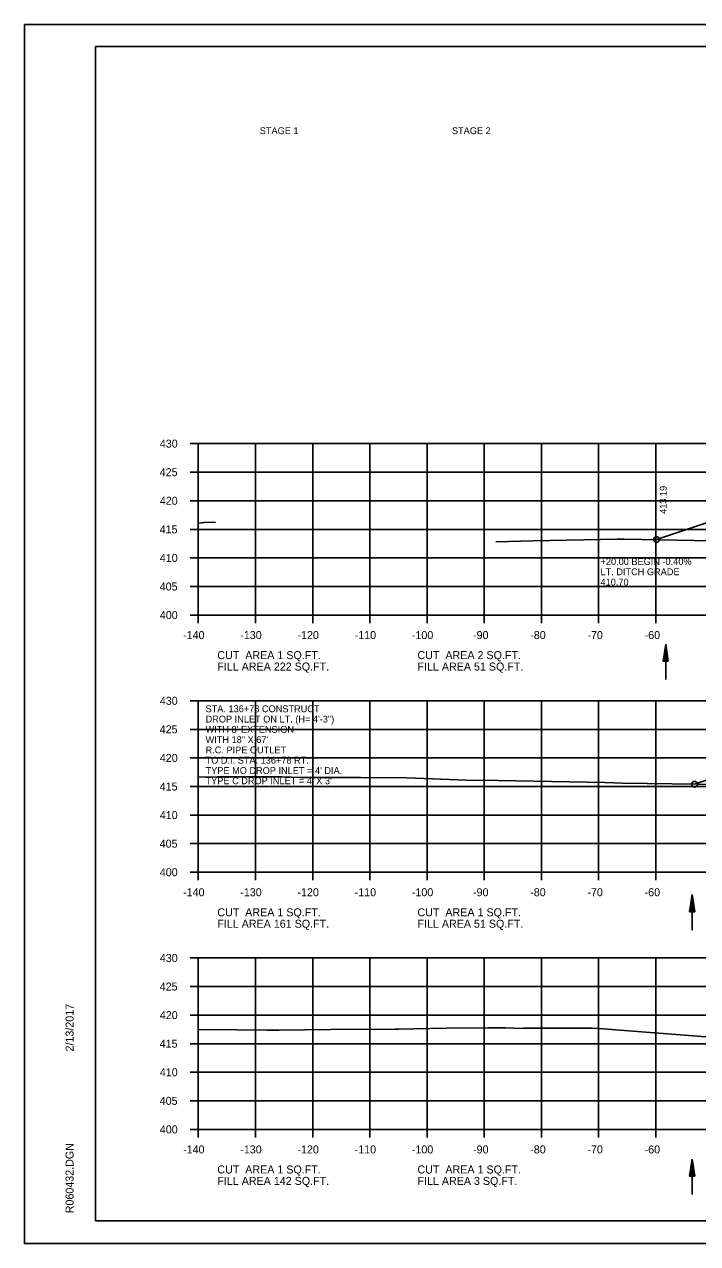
# Model space of a CAD drawing. Extents: x 1538688 to 1540766, y 656250 to 671912.
# Drawn here: x 1538687.8 to 1538805.5, y 661671.3 to 661884.7 of the extents above; entities that cross this region are included whole.
import ezdxf

# ---------------------------------------------------------------- set-up
doc = ezdxf.new("R2010")
doc.units = 0
for name, color, linetype in [('15', 7, 'Continuous'), ('18', 7, 'Continuous'), ('20', 7, 'Continuous'), ('22', 7, 'Continuous'), ('26', 7, 'Continuous'), ('39', 7, 'Continuous'), ('40', 7, 'Continuous'), ('41', 7, 'Continuous'), ('Borings', 7, 'Continuous'), ('Default', 7, 'Continuous'), ('Horizontal Alignment', 7, 'Continuous'), ('RipRap', 7, 'Continuous')]:
    doc.layers.add(name, color=color, linetype=linetype)

msp = doc.modelspace()

# ---------------------------------------------------------------- linework, layer by layer
at = {"layer": '15'}
for p, q in [((1538799.46, 661773.26), (1538799.91, 661776.26)), ((1538799.54, 661773.26), (1538799.91, 661775.76)), ((1538800.36, 661773.26), (1538799.91, 661776.26)), ((1538800.29, 661773.26), (1538799.91, 661775.76)), ((1538799.46, 661773.26), (1538800.36, 661773.26)), ((1538799.61, 661773.26), (1538799.91, 661775.24)), ((1538799.69, 661773.26), (1538799.91, 661774.74)), ((1538799.77, 661773.26), (1538799.91, 661774.24)), ((1538799.84, 661773.26), (1538799.91, 661773.73)), ((1538800.21, 661773.26), (1538799.91, 661775.24)), ((1538800.14, 661773.26), (1538799.91, 661774.74)), ((1538800.06, 661773.26), (1538799.91, 661774.24)), ((1538799.98, 661773.26), (1538799.91, 661773.73)), ((1538804.09, 661729.41), (1538804.54, 661732.41)), ((1538804.17, 661729.41), (1538804.54, 661731.91)), ((1538804.24, 661729.41), (1538804.54, 661731.39)), ((1538804.32, 661729.41), (1538804.54, 661730.89)), ((1538804.99, 661729.41), (1538804.54, 661732.41)), ((1538804.92, 661729.41), (1538804.54, 661731.91)), ((1538804.84, 661729.41), (1538804.54, 661731.39)), ((1538804.77, 661729.41), (1538804.54, 661730.89)), ((1538804.09, 661729.41), (1538804.99, 661729.41)), ((1538804.4, 661729.41), (1538804.54, 661730.38)), ((1538804.47, 661729.41), (1538804.54, 661729.88)), ((1538804.69, 661729.41), (1538804.54, 661730.38)), ((1538804.61, 661729.41), (1538804.54, 661729.88)), ((1538804.09, 661683.15), (1538804.54, 661686.15)), ((1538804.99, 661683.15), (1538804.54, 661686.15)), ((1538804.17, 661683.15), (1538804.54, 661685.65)), ((1538804.24, 661683.15), (1538804.54, 661685.14)), ((1538804.32, 661683.15), (1538804.54, 661684.64)), ((1538804.4, 661683.15), (1538804.54, 661684.13)), ((1538804.92, 661683.15), (1538804.54, 661685.65)), ((1538804.84, 661683.15), (1538804.54, 661685.14)), ((1538804.77, 661683.15), (1538804.54, 661684.64)), ((1538804.69, 661683.15), (1538804.54, 661684.13)), ((1538804.09, 661683.15), (1538804.99, 661683.15)), ((1538804.47, 661683.15), (1538804.54, 661683.63)), ((1538804.61, 661683.15), (1538804.54, 661683.63))]:
    msp.add_line(p, q, dxfattribs=at)
at = {"layer": '18'}
for points in [[(1538718.18, 661797.42), (1538719.22, 661797.53), (1538721.2, 661797.58)], [(1538770.19, 661794.16), (1538776.77, 661794.33), (1538791.41, 661794.6), (1538792.64, 661794.63), (1538807.97, 661794.34)], [(1538718.18, 661753.03), (1538718.2, 661753.03), (1538721.42, 661752.99), (1538721.56, 661753.01), (1538732.85, 661753.02), (1538736.02, 661752.93), (1538746.52, 661752.88), (1538754.65, 661752.85), (1538765.08, 661752.43), (1538770.59, 661752.36), (1538789.25, 661752.02), (1538792.37, 661751.89), (1538809.68, 661751.66)], [(1538718.18, 661708.83), (1538724.92, 661708.73), (1538730.21, 661708.69), (1538731.39, 661708.7), (1538732.31, 661708.68), (1538741.29, 661708.79), (1538752.54, 661708.88), (1538753.27, 661708.85), (1538755.88, 661708.94), (1538761.65, 661709.02), (1538768.86, 661709.1), (1538771.88, 661709.11), (1538774.68, 661709), (1538775.07, 661709.03), (1538786.4, 661709.06), (1538787.13, 661709.06), (1538788.24, 661708.98), (1538830.89, 661705.68)]]:
    msp.add_lwpolyline(points, dxfattribs=at)
at = {"layer": '20'}
for points in [[(1538798.28, 661794.53), (1538816.67, 661800.65), (1538821.67, 661800.55), (1538824.67, 661800.49), (1538825.17, 661800.49), (1538825.18, 661799.99), (1538826.18, 661800.01), (1538858.18, 661800.65), (1538890.18, 661800.01), (1538891.18, 661799.99), (1538891.19, 661800.49), (1538891.69, 661800.49), (1538894.69, 661800.55), (1538899.69, 661800.65), (1538914.02, 661795.88)], [(1538804.95, 661751.72), (1538816.67, 661755.63), (1538821.67, 661755.53), (1538824.67, 661755.47), (1538825.17, 661755.47), (1538825.18, 661754.97), (1538826.18, 661754.99), (1538858.18, 661755.63), (1538890.18, 661754.99), (1538891.18, 661754.97), (1538891.19, 661755.47), (1538891.69, 661755.47), (1538894.69, 661755.53), (1538899.69, 661755.63), (1538911.37, 661751.74)]]:
    msp.add_lwpolyline(points, dxfattribs=at)
at = {"layer": '22'}
for p, q in [((1538718.18, 661811.33), (1538998.18, 661811.33)), ((1538718.18, 661781.33), (1538718.18, 661811.33)), ((1538728.18, 661781.33), (1538728.18, 661811.33)), ((1538738.18, 661781.33), (1538738.18, 661811.33)), ((1538748.18, 661781.33), (1538748.18, 661811.33)), ((1538758.18, 661781.33), (1538758.18, 661811.33)), ((1538768.18, 661781.33), (1538768.18, 661811.33)), ((1538778.18, 661781.33), (1538778.18, 661811.33)), ((1538788.18, 661781.33), (1538788.18, 661811.33)), ((1538798.18, 661781.33), (1538798.18, 661811.33)), ((1538718.18, 661806.33), (1538998.18, 661806.33)), ((1538718.18, 661801.33), (1538998.18, 661801.33)), ((1538718.18, 661796.33), (1538998.18, 661796.33)), ((1538718.18, 661791.33), (1538998.18, 661791.33)), ((1538718.18, 661786.33), (1538998.18, 661786.33)), ((1538718.18, 661781.33), (1538998.18, 661781.33)), ((1538718.18, 661766.33), (1538998.18, 661766.33)), ((1538718.18, 661736.33), (1538718.18, 661766.33)), ((1538728.18, 661736.33), (1538728.18, 661766.33)), ((1538738.18, 661736.33), (1538738.18, 661766.33)), ((1538748.18, 661736.33), (1538748.18, 661766.33)), ((1538758.18, 661736.33), (1538758.18, 661766.33)), ((1538768.18, 661736.33), (1538768.18, 661766.33)), ((1538778.18, 661736.33), (1538778.18, 661766.33)), ((1538788.18, 661736.33), (1538788.18, 661766.33)), ((1538798.18, 661736.33), (1538798.18, 661766.33)), ((1538718.18, 661761.33), (1538998.18, 661761.33)), ((1538718.18, 661756.33), (1538998.18, 661756.33)), ((1538718.18, 661751.33), (1538998.18, 661751.33)), ((1538718.18, 661746.33), (1538998.18, 661746.33)), ((1538718.18, 661741.33), (1538998.18, 661741.33)), ((1538718.18, 661736.33), (1538998.18, 661736.33)), ((1538718.18, 661721.33), (1538998.18, 661721.33)), ((1538718.18, 661691.33), (1538718.18, 661721.33)), ((1538728.18, 661691.33), (1538728.18, 661721.33)), ((1538738.18, 661691.33), (1538738.18, 661721.33)), ((1538748.18, 661691.33), (1538748.18, 661721.33)), ((1538758.18, 661691.33), (1538758.18, 661721.33)), ((1538768.18, 661691.33), (1538768.18, 661721.33)), ((1538778.18, 661691.33), (1538778.18, 661721.33)), ((1538788.18, 661691.33), (1538788.18, 661721.33)), ((1538798.18, 661691.33), (1538798.18, 661721.33)), ((1538718.18, 661716.33), (1538998.18, 661716.33)), ((1538718.18, 661711.33), (1538998.18, 661711.33)), ((1538718.18, 661706.33), (1538998.18, 661706.33)), ((1538718.18, 661701.33), (1538998.18, 661701.33)), ((1538718.18, 661696.33), (1538998.18, 661696.33)), ((1538718.18, 661691.33), (1538998.18, 661691.33))]:
    msp.add_line(p, q, dxfattribs=at)
at = {"layer": '26'}
for p, q in [((1538687.78, 661884.68), (1539021.11, 661884.68)), ((1538687.78, 661671.35), (1539021.11, 661671.35))]:
    msp.add_line(p, q, dxfattribs=at)
msp.add_lwpolyline([(1538687.77, 661884.68), (1539021.11, 661884.68), (1539021.11, 661671.35), (1538687.77, 661671.35)], close=True, dxfattribs=at)
for centre in [(1538798.28, 661794.53), (1538804.95, 661751.72)]:
    msp.add_circle(centre, 0.5, dxfattribs=at)
at = {"layer": '39'}
for p, q in [((1538799.91, 661770.07), (1538799.91, 661776.26)), ((1538804.54, 661726.22), (1538804.54, 661732.41)), ((1538804.54, 661679.97), (1538804.54, 661686.15))]:
    msp.add_line(p, q, dxfattribs=at)
at = {"layer": 'Borings'}
for p, q in [((1538716.78, 661811.33), (1538718.18, 661811.33)), ((1538718.18, 661781.33), (1538718.18, 661811.33)), ((1538716.78, 661806.33), (1538718.18, 661806.33)), ((1538716.78, 661801.33), (1538718.18, 661801.33)), ((1538716.78, 661796.33), (1538718.18, 661796.33)), ((1538716.78, 661791.33), (1538718.18, 661791.33)), ((1538716.78, 661786.33), (1538718.18, 661786.33)), ((1538716.78, 661781.33), (1538718.18, 661781.33)), ((1538718.18, 661781.33), (1538998.18, 661781.33)), ((1538718.18, 661779.93), (1538718.18, 661781.33)), ((1538728.18, 661779.93), (1538728.18, 661781.33)), ((1538738.18, 661779.93), (1538738.18, 661781.33)), ((1538748.18, 661779.93), (1538748.18, 661781.33)), ((1538758.18, 661779.93), (1538758.18, 661781.33)), ((1538768.18, 661779.93), (1538768.18, 661781.33)), ((1538778.18, 661779.93), (1538778.18, 661781.33)), ((1538788.18, 661779.93), (1538788.18, 661781.33)), ((1538798.18, 661779.93), (1538798.18, 661781.33)), ((1538716.78, 661766.33), (1538718.18, 661766.33)), ((1538718.18, 661736.33), (1538718.18, 661766.33)), ((1538716.78, 661761.33), (1538718.18, 661761.33)), ((1538716.78, 661756.33), (1538718.18, 661756.33)), ((1538716.78, 661751.33), (1538718.18, 661751.33)), ((1538716.78, 661746.33), (1538718.18, 661746.33)), ((1538716.78, 661741.33), (1538718.18, 661741.33)), ((1538716.78, 661736.33), (1538718.18, 661736.33)), ((1538718.18, 661736.33), (1538998.18, 661736.33)), ((1538718.18, 661734.93), (1538718.18, 661736.33)), ((1538728.18, 661734.93), (1538728.18, 661736.33)), ((1538738.18, 661734.93), (1538738.18, 661736.33)), ((1538748.18, 661734.93), (1538748.18, 661736.33)), ((1538758.18, 661734.93), (1538758.18, 661736.33)), ((1538768.18, 661734.93), (1538768.18, 661736.33)), ((1538778.18, 661734.93), (1538778.18, 661736.33)), ((1538788.18, 661734.93), (1538788.18, 661736.33)), ((1538798.18, 661734.93), (1538798.18, 661736.33)), ((1538716.78, 661721.33), (1538718.18, 661721.33)), ((1538718.18, 661691.33), (1538718.18, 661721.33)), ((1538716.78, 661716.33), (1538718.18, 661716.33)), ((1538716.78, 661711.33), (1538718.18, 661711.33)), ((1538716.78, 661706.33), (1538718.18, 661706.33)), ((1538716.78, 661701.33), (1538718.18, 661701.33)), ((1538716.78, 661696.33), (1538718.18, 661696.33)), ((1538716.78, 661691.33), (1538718.18, 661691.33)), ((1538718.18, 661691.33), (1538998.18, 661691.33)), ((1538718.18, 661689.93), (1538718.18, 661691.33)), ((1538728.18, 661689.93), (1538728.18, 661691.33)), ((1538738.18, 661689.93), (1538738.18, 661691.33)), ((1538748.18, 661689.93), (1538748.18, 661691.33)), ((1538758.18, 661689.93), (1538758.18, 661691.33)), ((1538768.18, 661689.93), (1538768.18, 661691.33)), ((1538778.18, 661689.93), (1538778.18, 661691.33)), ((1538788.18, 661689.93), (1538788.18, 661691.33)), ((1538798.18, 661689.93), (1538798.18, 661691.33))]:
    msp.add_line(p, q, dxfattribs=at)
at = {"layer": 'RipRap'}
for p, q in [((1538700.18, 661880.79), (1539016.36, 661880.79)), ((1538700.18, 661675.33), (1538700.18, 661880.79)), ((1538700.18, 661675.33), (1538700.18, 661675.33)), ((1539016.36, 661675.33), (1538700.18, 661675.33))]:
    msp.add_line(p, q, dxfattribs=at)

# ---------------------------------------------------------------- texts
at = {"layer": '40'}
for s, p in [('+20.00 BEGIN -0.40%', (1538788.51, 661790.1)), ('LT. DITCH GRADE', (1538788.51, 661788.3)), ('410.70', (1538788.51, 661786.5)), ('STA. 136+78 CONSTRUCT', (1538719.45, 661764.33)), ('DROP INLET ON LT. (H= 4\'-3")', (1538719.45, 661762.53)), ("WITH 8' EXTENSION", (1538719.45, 661760.73)), ('WITH 18" X 67\'', (1538719.45, 661758.93)), ('R.C. PIPE OUTLET', (1538719.45, 661757.13)), ('TO D.I. STA. 136+78 RT.', (1538719.45, 661755.33)), ("TYPE MO DROP INLET = 4' DIA.", (1538719.45, 661753.53)), ("TYPE C DROP INLET = 4' X 3'", (1538719.45, 661751.73))]:
    msp.add_text(s, height=1.2, dxfattribs=at).set_placement(p)
at = {"layer": '41'}
msp.add_text('413.19', height=1.2, rotation=90, dxfattribs=at).set_placement((1538800.08, 661799.03))
at = {"layer": 'Default'}
for s, p in [('STAGE 1', (1538728.93, 661865.48)), ('STAGE 2', (1538762.53, 661865.48))]:
    msp.add_text(s, height=1.2, dxfattribs=at).set_placement(p)
at = {"layer": 'Horizontal Alignment'}
for s, p in [('430', (1538711.45, 661810.63)), ('425', (1538711.43, 661805.63)), ('420', (1538711.45, 661800.63)), ('415', (1538711.43, 661795.63)), ('410', (1538711.45, 661790.63)), ('405', (1538711.43, 661785.63)), ('400', (1538711.45, 661780.63)), ('-140', (1538715.52, 661777.13)), ('-130', (1538725.52, 661777.13)), ('-120', (1538735.52, 661777.13)), ('-110', (1538745.52, 661777.13)), ('-100', (1538755.52, 661777.13)), ('-90', (1538766.22, 661777.13)), ('-80', (1538776.22, 661777.13)), ('-70', (1538786.22, 661777.13)), ('-60', (1538796.22, 661777.13)), ('CUT  AREA 1 SQ.FT.', (1538721.5, 661773.62)), ('CUT  AREA 2 SQ.FT.', (1538756.5, 661773.62)), ('FILL AREA 222 SQ.FT.', (1538721.5, 661771.62)), ('FILL AREA 51 SQ.FT.', (1538756.5, 661771.62)), ('430', (1538711.45, 661765.63)), ('425', (1538711.43, 661760.63)), ('420', (1538711.45, 661755.63)), ('415', (1538711.43, 661750.63)), ('410', (1538711.45, 661745.63)), ('405', (1538711.43, 661740.63)), ('400', (1538711.45, 661735.63)), ('-140', (1538715.52, 661732.13)), ('-130', (1538725.52, 661732.13)), ('-120', (1538735.52, 661732.13)), ('-110', (1538745.52, 661732.13)), ('-100', (1538755.52, 661732.13)), ('-90', (1538766.22, 661732.13)), ('-80', (1538776.22, 661732.13)), ('-70', (1538786.22, 661732.13)), ('-60', (1538796.22, 661732.13)), ('CUT  AREA 1 SQ.FT.', (1538721.5, 661728.62)), ('CUT  AREA 1 SQ.FT.', (1538756.5, 661728.62)), ('FILL AREA 161 SQ.FT.', (1538721.5, 661726.62)), ('FILL AREA 51 SQ.FT.', (1538756.5, 661726.62)), ('430', (1538711.45, 661720.63)), ('425', (1538711.43, 661715.63)), ('420', (1538711.45, 661710.63)), ('415', (1538711.43, 661705.63)), ('410', (1538711.45, 661700.63)), ('405', (1538711.43, 661695.63)), ('400', (1538711.45, 661690.63)), ('-140', (1538715.52, 661687.13)), ('-130', (1538725.52, 661687.13)), ('-120', (1538735.52, 661687.13)), ('-110', (1538745.52, 661687.13)), ('-100', (1538755.52, 661687.13)), ('-90', (1538766.22, 661687.13)), ('-80', (1538776.22, 661687.13)), ('-70', (1538786.22, 661687.13)), ('-60', (1538796.22, 661687.13)), ('CUT  AREA 1 SQ.FT.', (1538721.5, 661683.62)), ('CUT  AREA 1 SQ.FT.', (1538756.5, 661683.62)), ('FILL AREA 142 SQ.FT.', (1538721.5, 661681.62)), ('FILL AREA 3 SQ.FT.', (1538756.5, 661681.62))]:
    msp.add_text(s, height=1.4, dxfattribs=at).set_placement(p)
at = {"layer": 'RipRap'}
for s, p in [('2/13/2017', (1538696.37, 661704.97)), ('R060432.DGN', (1538696.37, 661676.66))]:
    msp.add_text(s, height=1.4, rotation=90, dxfattribs=at).set_placement(p)

doc.saveas('drawing.dxf')
